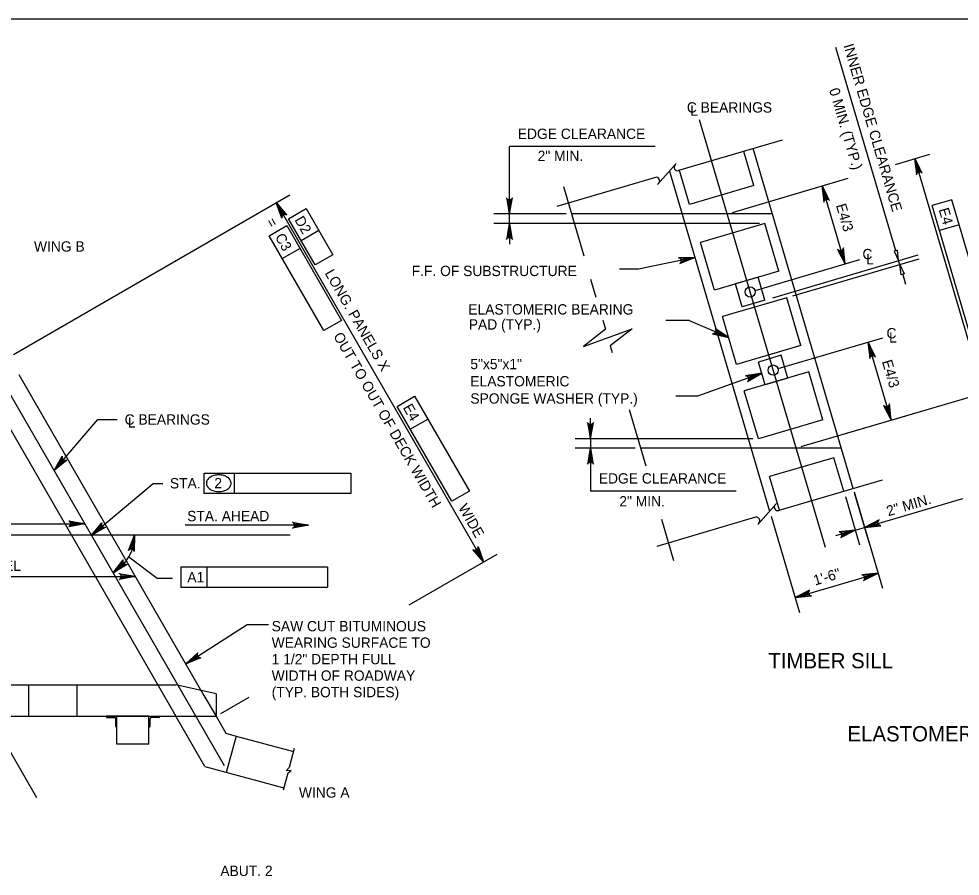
# Model space of a CAD drawing. Extents: x 638268 to 640277, y 295465 to 298435.
# Drawn here: x 639628.9 to 639902.1, y 296983.7 to 297232.5 of the extents above; entities that cross this region are included whole.
import ezdxf

# ---------------------------------------------------------------- set-up
doc = ezdxf.new("R2010")
doc.units = 0
for name, color, linetype in [('2', 7, 'Continuous'), ('3', 7, 'Continuous'), ('4', 7, 'Continuous'), ('7', 7, 'Continuous')]:
    doc.layers.add(name, color=color, linetype=linetype)

msp = doc.modelspace()

# ---------------------------------------------------------------- linework, layer by layer
at = {"layer": '2'}
for p, q in [((639316.46, 297232.46), (640102.46, 297232.46)), ((639614.31, 297134.29), (639674.49, 297030.06)), ((639628.88, 297129.24), (639682.63, 297036.13)), ((639539.28, 297039.18), (639674.46, 297039.18)), ((639631.81, 297030.06), (639631.81, 297039.18)), ((639645.83, 297030.06), (639645.83, 297039.18)), ((639686.14, 297036.58), (639674.46, 297039.18)), ((639686.14, 297036.58), (639686.14, 297030.06)), ((639682.63, 297036.13), (639686.14, 297030.06)), ((639492.13, 297030.06), (639686.14, 297030.06)), ((639492.13, 297030.06), (639686.14, 297030.06)), ((639654.29, 297029.88), (639654.29, 297030.06)), ((639657.38, 297030.06), (639654.29, 297030.06)), ((639654.48, 297029.7), (639656.66, 297029.7)), ((639657.02, 297027.15), (639657.02, 297029.33)), ((639666.62, 297030.06), (639657.38, 297030.06)), ((639657.38, 297026.97), (639657.38, 297030.06)), ((639657.38, 297021.97), (639657.38, 297030.06)), ((639666.62, 297026.97), (639666.62, 297030.06)), ((639666.62, 297030.06), (639669.71, 297030.06)), ((639666.62, 297021.97), (639666.62, 297030.06)), ((639666.98, 297027.15), (639666.98, 297029.33)), ((639669.53, 297029.7), (639667.35, 297029.7)), ((639669.71, 297029.88), (639669.71, 297030.06)), ((639682.91, 297015.46), (639674.49, 297030.06)), ((639686.14, 297030.06), (639688.98, 297025.13)), ((639657.2, 297026.97), (639657.38, 297026.97)), ((639666.8, 297026.97), (639666.62, 297026.97)), ((639688.98, 297025.13), (639691.94, 297024.34)), ((639691.94, 297024.34), (639689.11, 297013.8)), ((639691.94, 297024.34), (639708.62, 297019.87)), ((639666.62, 297021.97), (639657.38, 297021.97)), ((639682.91, 297015.46), (639705.79, 297009.33))]:
    msp.add_line(p, q, dxfattribs=at)
for centre, radius, start, end in [((639654.48, 297029.88), 0.182, 180.0016, 270), ((639656.66, 297029.33), 0.364, 0.0016, 90), ((639667.35, 297029.33), 0.364, 90, 179.9984), ((639669.53, 297029.88), 0.182, 270, 359.9984), ((639657.2, 297027.15), 0.182, 180.0016, 270), ((639666.8, 297027.15), 0.182, 270, 359.9984)]:
    msp.add_arc(centre, radius, start, end, dxfattribs=at)
at = {"layer": '3'}
for p, q in [((639850.43, 297197.27), (639820.41, 297188.43)), ((639871.06, 297096.14), (639842.01, 297194.79)), ((639883.33, 297190.23), (639893.29, 297193.16)), ((639819.72, 297190.5), (639814.31, 297184.36)), ((639908.99, 297123.91), (639888.97, 297191.89)), ((639813.71, 297186.46), (639785.03, 297178.01)), ((639817.76, 297188.28), (639846.82, 297089.63)), ((639786.97, 297183.81), (639792.9, 297163.67)), ((639842.23, 297184.11), (639823.54, 297178.6)), ((639836.01, 297176.29), (639869.64, 297186.19)), ((639847.59, 297175.85), (639789.32, 297175.85)), ((639845.48, 297173.09), (639826.78, 297167.59)), ((639847.72, 297151.52), (639889.91, 297163.95)), ((639853.53, 297152.03), (639890.23, 297162.85)), ((639849.55, 297159.25), (639830.86, 297153.74)), ((639794.88, 297156.95), (639796.43, 297151.7)), ((639843.51, 297157.46), (639836.9, 297155.52)), ((639851.83, 297151.53), (639833.13, 297146.03)), ((639845.46, 297150.86), (639838.85, 297148.91)), ((639798.4, 297145.01), (639799.17, 297142.38)), ((639800.59, 297137.59), (639801.16, 297135.65)), ((639855.9, 297137.69), (639837.21, 297132.18)), ((639850.19, 297134.81), (639843.58, 297132.86)), ((639858.18, 297129.98), (639839.48, 297124.47)), ((639852.13, 297128.2), (639845.53, 297126.25)), ((639856.03, 297108.31), (639913.31, 297125.18)), ((639806.04, 297119.06), (639810.85, 297102.76)), ((639862.25, 297116.13), (639843.56, 297110.62)), ((639867.61, 297107.87), (639809.34, 297107.87)), ((639865.5, 297105.11), (639846.81, 297099.61)), ((639879.48, 297098.62), (639849.47, 297089.78)), ((639848.78, 297091.85), (639843.36, 297085.71)), ((639842.76, 297087.81), (639814.08, 297079.36)), ((639815.4, 297087.29), (639818.93, 297075.3)), ((639708.84, 297020.69), (639707.37, 297015.22)), ((639706.5, 297014.27), (639707.37, 297015.22)), ((639707.96, 297014.36), (639706.5, 297014.27)), ((639706.93, 297013.59), (639707.96, 297014.36)), ((639706.93, 297013.59), (639705.59, 297008.59))]:
    msp.add_line(p, q, dxfattribs=at)
msp.add_lwpolyline([(639890.3, 297189.15), (639889.34, 297188.87), (639888.97, 297191.89)], close=True, dxfattribs=at)
for centre, start, end in [((639820.13, 297189.41), 136.412, 286.412), ((639813.9, 297185.45), 318.5448, 101.0834), ((639849.18, 297090.76), 136.412, 286.412), ((639842.96, 297086.8), 318.5448, 101.0834)]:
    msp.add_arc(centre, 1.02, start, end, dxfattribs=at)
at = {"layer": '4'}
for p, q in [((639883.43, 297165.17), (639866.06, 297224.16)), ((639863.01, 297079.06), (639826.47, 297203.14)), ((639771.31, 297178.85), (639771.31, 297195.39)), ((639813.58, 297195.39), (639771.31, 297195.39)), ((639688.63, 297015.66), (639589.95, 297186.58)), ((639836.01, 297176.29), (639866.38, 297185.23)), ((639868.74, 297161.3), (639862.06, 297183.96)), ((639627.32, 297135.07), (639707.53, 297181.38)), ((639703.63, 297179.13), (639763.8, 297074.9)), ((639899.69, 297179.91), (639894.03, 297178.24)), ((639906.04, 297137.45), (639894.03, 297178.24)), ((639911.7, 297139.12), (639899.69, 297179.91)), ((639707.2, 297174.46), (639712.32, 297177.42)), ((639712.32, 297177.42), (639720.06, 297164)), ((639787.75, 297175.85), (639766.81, 297175.85)), ((639771.31, 297173.09), (639771.31, 297175.85)), ((639714.95, 297161.05), (639707.2, 297174.46)), ((639843.91, 297173.09), (639766.81, 297173.09)), ((639701.52, 297169.49), (639706.64, 297172.44)), ((639706.64, 297172.44), (639722.53, 297144.92)), ((639710.84, 297168.16), (639715.96, 297171.11)), ((639771.31, 297170.09), (639771.31, 297167.09)), ((639901.83, 297172.65), (639896.16, 297170.99)), ((639717.41, 297141.97), (639701.52, 297169.49)), ((639705.35, 297162.87), (639710.46, 297165.82)), ((639720.06, 297164), (639714.95, 297161.05)), ((639842.68, 297153.63), (639873.05, 297162.57)), ((639884.6, 297161.19), (639884.28, 297162.29)), ((639808.76, 297159.78), (639803.23, 297159.78)), ((639885.45, 297158.31), (639886.3, 297155.43)), ((639722.53, 297144.92), (639717.41, 297141.97)), ((639823.57, 297144.87), (639816.72, 297144.87)), ((639849.35, 297130.97), (639879.73, 297139.91)), ((639882.08, 297115.98), (639875.41, 297138.64)), ((639738.67, 297119.98), (639743.78, 297122.93)), ((639743.78, 297122.93), (639759.67, 297095.41)), ((639825.95, 297122.92), (639819.57, 297122.92)), ((639754.56, 297092.46), (639738.67, 297119.98)), ((639639.12, 297101.41), (639651.85, 297116.15)), ((639651.85, 297116.15), (639657.47, 297116.15)), ((639742.49, 297113.35), (639747.61, 297116.31)), ((639794.84, 297113.62), (639794.84, 297116.62)), ((639856.03, 297108.31), (639886.4, 297117.26)), ((639842, 297110.62), (639790.34, 297110.62)), ((639794.84, 297110.62), (639794.84, 297107.87)), ((639807.78, 297107.87), (639790.34, 297107.87)), ((639794.84, 297104.87), (639794.84, 297095.4)), ((639682.7, 297094.75), (639682.7, 297100.65)), ((639682.7, 297100.65), (639725.22, 297100.65)), ((639691.45, 297094.75), (639691.45, 297100.65)), ((639725.22, 297100.65), (639725.22, 297094.75)), ((639649.99, 297082.58), (639667.92, 297097.57)), ((639667.92, 297097.57), (639670.69, 297097.57)), ((639725.22, 297094.75), (639682.7, 297094.75)), ((639759.67, 297095.41), (639754.56, 297092.46)), ((639837.1, 297095.4), (639794.84, 297095.4)), ((639868.82, 297093.85), (639872.96, 297079.78)), ((639871.34, 297095.22), (639879.57, 297067.28)), ((639871.51, 297094.65), (639875.65, 297080.57)), ((639874.38, 297084.88), (639902.9, 297093.29)), ((639847.26, 297088.13), (639855.49, 297060.19)), ((639468.6, 297085.95), (639648.04, 297085.95)), ((639713.02, 297085.52), (639677.21, 297085.52)), ((639871.69, 297084.09), (639865.94, 297082.4)), ((639871.69, 297084.09), (639874.38, 297084.89)), ((639707.69, 297082.58), (639405.47, 297082.58)), ((639742.18, 297062.42), (639767.7, 297077.15)), ((639660.83, 297076.32), (639669.01, 297070.11)), ((639675.94, 297073.48), (639718.45, 297073.48)), ((639675.94, 297073.48), (639675.94, 297067.58)), ((639683.5, 297073.48), (639683.5, 297067.58)), ((639718.45, 297073.48), (639718.45, 297067.58)), ((639471.61, 297070.65), (639662.7, 297070.65)), ((639669.01, 297070.11), (639673.48, 297070.11)), ((639854.22, 297064.5), (639878.3, 297071.6)), ((639598.34, 297068.34), (639634.03, 297006.52)), ((639675.94, 297067.58), (639718.45, 297067.58)), ((639677.37, 297045.24), (639695.2, 297056.69)), ((639695.2, 297056.69), (639701.39, 297056.69)), ((639687.49, 297030.84), (639695.73, 297035.6))]:
    msp.add_line(p, q, dxfattribs=at)
for points in [[(639888.97, 297191.89), (639889.45, 297187.17), (639889.59, 297187.59), (639889.83, 297187.85), (639890.12, 297187.99), (639890.43, 297188.03), (639890.78, 297187.94), (639891.12, 297187.67), (639888.97, 297191.89), (639890.78, 297187.94), (639890.43, 297188.03), (639888.97, 297191.89), (639890.12, 297187.99), (639889.83, 297187.85), (639888.97, 297191.89), (639889.59, 297187.59)], [(639862.06, 297183.96), (639862.54, 297179.25), (639862.68, 297179.66), (639862.92, 297179.92), (639863.21, 297180.06), (639863.52, 297180.1), (639863.88, 297180.01), (639864.21, 297179.74), (639862.06, 297183.96), (639863.88, 297180.01), (639863.52, 297180.1), (639862.06, 297183.96), (639863.21, 297180.06), (639862.92, 297179.92), (639862.06, 297183.96), (639862.68, 297179.66)], [(639703.63, 297179.13), (639706.72, 297175.53), (639706.32, 297175.71), (639705.96, 297175.72), (639705.66, 297175.61), (639705.42, 297175.41), (639705.24, 297175.09), (639705.2, 297174.65), (639703.63, 297179.13), (639705.24, 297175.09), (639705.42, 297175.41), (639703.63, 297179.13), (639705.66, 297175.61), (639705.96, 297175.72), (639703.63, 297179.13), (639706.32, 297175.71)], [(639771.31, 297175.85), (639772.19, 297180.51), (639771.94, 297180.15), (639771.63, 297179.96), (639771.31, 297179.91), (639771, 297179.96), (639770.69, 297180.15), (639770.44, 297180.51), (639771.31, 297175.85), (639770.69, 297180.15), (639771, 297179.96), (639771.31, 297175.85), (639771.31, 297179.91), (639771.63, 297179.96), (639771.31, 297175.85), (639771.94, 297180.15)], [(639771.31, 297173.09), (639770.44, 297168.43), (639770.69, 297168.79), (639771, 297168.97), (639771.31, 297169.03), (639771.63, 297168.97), (639771.94, 297168.79), (639772.19, 297168.43), (639771.31, 297173.09), (639771.94, 297168.79), (639771.63, 297168.97), (639771.31, 297173.09), (639771.31, 297169.03), (639771, 297168.97), (639771.31, 297173.09), (639770.69, 297168.79)], [(639868.74, 297161.3), (639868.26, 297166.02), (639868.12, 297165.61), (639867.87, 297165.34), (639867.59, 297165.2), (639867.27, 297165.16), (639866.92, 297165.25), (639866.58, 297165.53), (639868.74, 297161.3), (639866.92, 297165.25), (639867.27, 297165.16), (639868.74, 297161.3), (639867.59, 297165.2), (639867.87, 297165.34), (639868.74, 297161.3), (639868.12, 297165.61)], [(639825.14, 297163.23), (639808.76, 297159.78)], [(639825.14, 297163.23), (639820.4, 297163.12), (639820.8, 297162.96), (639821.05, 297162.69), (639821.17, 297162.39), (639821.18, 297162.08), (639821.06, 297161.73), (639820.76, 297161.42), (639825.14, 297163.23), (639821.06, 297161.73), (639821.18, 297162.08), (639825.14, 297163.23), (639821.17, 297162.39), (639821.05, 297162.69), (639825.14, 297163.23), (639820.8, 297162.96)], [(639834.91, 297139.97), (639823.41, 297144.94)], [(639799.17, 297142.38), (639792.84, 297137.35), (639806.97, 297142.45), (639800.58, 297137.59)], [(639834.91, 297139.97), (639830.98, 297142.62), (639831.21, 297142.25), (639831.26, 297141.89), (639831.19, 297141.58), (639831.01, 297141.32), (639830.72, 297141.11), (639830.29, 297141.02), (639834.91, 297139.97), (639830.72, 297141.11), (639831.01, 297141.32), (639834.91, 297139.97), (639831.19, 297141.58), (639831.26, 297141.89), (639834.91, 297139.97), (639831.21, 297142.25)], [(639875.41, 297138.64), (639875.89, 297133.93), (639876.03, 297134.34), (639876.27, 297134.61), (639876.56, 297134.75), (639876.87, 297134.78), (639877.22, 297134.69), (639877.56, 297134.42), (639875.41, 297138.64), (639877.22, 297134.69), (639876.87, 297134.78), (639875.41, 297138.64), (639876.56, 297134.75), (639876.27, 297134.61), (639875.41, 297138.64), (639876.03, 297134.34)], [(639844.54, 297129.61), (639825.94, 297122.92)], [(639844.54, 297129.61), (639839.85, 297128.85), (639840.28, 297128.74), (639840.56, 297128.51), (639840.71, 297128.23), (639840.77, 297127.92), (639840.7, 297127.56), (639840.45, 297127.21), (639844.54, 297129.61), (639840.7, 297127.56), (639840.77, 297127.92), (639844.54, 297129.61), (639840.71, 297128.23), (639840.56, 297128.51), (639844.54, 297129.61), (639840.28, 297128.74)], [(639882.08, 297115.98), (639881.6, 297120.7), (639881.47, 297120.29), (639881.22, 297120.02), (639880.94, 297119.88), (639880.62, 297119.85), (639880.27, 297119.93), (639879.93, 297120.21), (639882.08, 297115.98), (639880.27, 297119.93), (639880.62, 297119.85), (639882.08, 297115.98), (639880.94, 297119.88), (639881.22, 297120.02), (639882.08, 297115.98), (639881.47, 297120.29)], [(639794.84, 297110.62), (639795.71, 297115.28), (639795.46, 297114.93), (639795.15, 297114.74), (639794.84, 297114.69), (639794.52, 297114.74), (639794.21, 297114.93), (639793.96, 297115.28), (639794.84, 297110.62), (639794.21, 297114.93), (639794.52, 297114.74), (639794.84, 297110.62), (639794.84, 297114.69), (639795.15, 297114.74), (639794.84, 297110.62), (639795.46, 297114.93)], [(639794.84, 297107.87), (639793.96, 297103.21), (639794.21, 297103.57), (639794.52, 297103.75), (639794.84, 297103.81), (639795.15, 297103.75), (639795.46, 297103.57), (639795.71, 297103.21), (639794.84, 297107.87), (639795.46, 297103.57), (639795.15, 297103.75), (639794.84, 297107.87), (639794.84, 297103.81), (639794.52, 297103.75), (639794.84, 297107.87), (639794.21, 297103.57)], [(639639.12, 297101.41), (639641.5, 297105.51), (639641.46, 297105.07), (639641.57, 297104.73), (639641.77, 297104.48), (639642.05, 297104.32), (639642.4, 297104.26), (639642.83, 297104.36), (639639.12, 297101.41), (639642.4, 297104.26), (639642.05, 297104.32), (639639.12, 297101.41), (639641.77, 297104.48), (639641.57, 297104.73), (639639.12, 297101.41), (639641.46, 297105.07)], [(639648.04, 297085.95), (639643.38, 297085.08), (639643.74, 297085.33), (639643.93, 297085.64), (639643.98, 297085.95), (639643.93, 297086.27), (639643.74, 297086.58), (639643.38, 297086.83), (639648.04, 297085.95), (639643.74, 297086.58), (639643.93, 297086.27), (639648.04, 297085.95), (639643.98, 297085.95), (639643.93, 297085.64), (639648.04, 297085.95), (639643.74, 297085.33)], [(639649.99, 297082.58), (639653, 297086.24), (639652.89, 297085.82), (639652.95, 297085.46), (639653.11, 297085.19), (639653.35, 297084.98), (639653.69, 297084.86), (639654.12, 297084.9), (639649.99, 297082.58), (639653.69, 297084.86), (639653.35, 297084.98), (639649.99, 297082.58), (639653.11, 297085.19), (639652.95, 297085.46), (639649.99, 297082.58), (639652.89, 297085.82)], [(639713.02, 297085.52), (639708.36, 297084.65), (639708.72, 297084.89), (639708.91, 297085.21), (639708.96, 297085.52), (639708.91, 297085.83), (639708.72, 297086.14), (639708.36, 297086.39), (639713.02, 297085.52), (639708.72, 297086.14), (639708.91, 297085.83), (639713.02, 297085.52), (639708.96, 297085.52), (639708.91, 297085.21), (639713.02, 297085.52), (639708.72, 297084.89)], [(639874.38, 297084.88), (639879.1, 297085.36), (639878.68, 297085.5), (639878.42, 297085.75), (639878.28, 297086.03), (639878.24, 297086.35), (639878.33, 297086.7), (639878.6, 297087.04), (639874.38, 297084.88), (639878.33, 297086.7), (639878.24, 297086.35), (639874.38, 297084.88), (639878.28, 297086.03), (639878.42, 297085.75), (639874.38, 297084.88), (639878.68, 297085.5)], [(639871.69, 297084.09), (639866.98, 297083.61), (639867.39, 297083.48), (639867.65, 297083.23), (639867.79, 297082.95), (639867.83, 297082.63), (639867.74, 297082.28), (639867.47, 297081.94), (639871.69, 297084.09), (639867.74, 297082.28), (639867.83, 297082.63), (639871.69, 297084.09), (639867.79, 297082.95), (639867.65, 297083.23), (639871.69, 297084.09), (639867.39, 297083.48)], [(639662.51, 297082.58), (639662.4, 297077.84), (639662.23, 297078.24), (639661.96, 297078.49), (639661.67, 297078.61), (639661.35, 297078.62), (639661.01, 297078.5), (639660.69, 297078.2), (639662.51, 297082.58), (639661.01, 297078.5), (639661.35, 297078.62), (639662.51, 297082.58), (639661.67, 297078.61), (639661.96, 297078.49), (639662.51, 297082.58), (639662.23, 297078.24)], [(639763.8, 297074.9), (639760.72, 297078.5), (639761.11, 297078.31), (639761.48, 297078.31), (639761.77, 297078.42), (639762.02, 297078.62), (639762.2, 297078.94), (639762.23, 297079.37), (639763.8, 297074.9), (639762.2, 297078.94), (639762.02, 297078.62), (639763.8, 297074.9), (639761.77, 297078.42), (639761.48, 297078.31), (639763.8, 297074.9), (639761.11, 297078.31)], [(639656.25, 297071.74), (639659.2, 297075.45), (639659.1, 297075.03), (639659.16, 297074.67), (639659.32, 297074.4), (639659.57, 297074.19), (639659.91, 297074.08), (639660.35, 297074.13), (639656.25, 297071.74), (639659.91, 297074.08), (639659.57, 297074.19), (639656.25, 297071.74), (639659.32, 297074.4), (639659.16, 297074.67), (639656.25, 297071.74), (639659.1, 297075.03)], [(639662.7, 297070.65), (639658.04, 297069.78), (639658.4, 297070.03), (639658.59, 297070.34), (639658.64, 297070.65), (639658.59, 297070.96), (639658.4, 297071.28), (639658.04, 297071.52), (639662.7, 297070.65), (639658.4, 297071.28), (639658.59, 297070.96), (639662.7, 297070.65), (639658.64, 297070.65), (639658.59, 297070.34), (639662.7, 297070.65), (639658.4, 297070.03)], [(639878.3, 297071.6), (639873.58, 297071.12), (639873.99, 297070.98), (639874.26, 297070.73), (639874.4, 297070.45), (639874.44, 297070.13), (639874.35, 297069.78), (639874.07, 297069.44), (639878.3, 297071.6), (639874.35, 297069.78), (639874.44, 297070.13), (639878.3, 297071.6), (639874.4, 297070.45), (639874.26, 297070.73), (639878.3, 297071.6), (639873.99, 297070.98)], [(639854.22, 297064.5), (639858.94, 297064.98), (639858.52, 297065.12), (639858.26, 297065.37), (639858.12, 297065.65), (639858.08, 297065.97), (639858.17, 297066.32), (639858.44, 297066.66), (639854.22, 297064.5), (639858.17, 297066.32), (639858.08, 297065.97), (639854.22, 297064.5), (639858.12, 297065.65), (639858.26, 297065.37), (639854.22, 297064.5), (639858.52, 297065.12)], [(639677.37, 297045.24), (639680.82, 297048.49), (639680.66, 297048.09), (639680.67, 297047.73), (639680.79, 297047.43), (639681.01, 297047.2), (639681.33, 297047.04), (639681.77, 297047.02), (639677.37, 297045.24), (639681.33, 297047.04), (639681.01, 297047.2), (639677.37, 297045.24), (639680.79, 297047.43), (639680.67, 297047.73), (639677.37, 297045.24), (639680.66, 297048.09)]]:
    msp.add_lwpolyline(points, dxfattribs=at)
for points in [[(639863.39, 297181.23), (639862.43, 297180.94), (639862.06, 297183.96)], [(639705.56, 297176.78), (639704.7, 297176.28), (639703.63, 297179.13)], [(639771.81, 297178.85), (639770.81, 297178.85), (639771.31, 297175.85)], [(639771.81, 297170.09), (639770.81, 297170.09), (639771.31, 297173.09)], [(639883.91, 297165.31), (639882.95, 297165.03), (639884.28, 297162.29)], [(639825.14, 297163.23), (639822.26, 297162.37), (639822.15, 297162.86)], [(639868.37, 297164.32), (639867.41, 297164.04), (639868.74, 297161.3)], [(639885.93, 297158.45), (639884.97, 297158.17), (639884.6, 297161.19)], [(639834.91, 297139.97), (639832.06, 297140.93), (639832.26, 297141.39)], [(639876.74, 297135.91), (639875.78, 297135.62), (639875.41, 297138.64)], [(639844.54, 297129.61), (639841.8, 297128.36), (639841.63, 297128.83)], [(639881.71, 297119), (639880.76, 297118.72), (639882.08, 297115.98)], [(639795.34, 297113.62), (639794.34, 297113.62), (639794.84, 297110.62)], [(639795.34, 297104.87), (639794.34, 297104.87), (639794.84, 297107.87)], [(639877.12, 297086.21), (639877.4, 297085.25), (639874.38, 297084.89)], [(639651.82, 297084.71), (639652.41, 297084), (639649.99, 297082.58)], [(639868.67, 297083.73), (639868.95, 297082.77), (639871.69, 297084.09)], [(639762.74, 297077.75), (639761.87, 297077.25), (639763.8, 297074.9)], [(639875.28, 297071.23), (639875.56, 297070.27), (639878.3, 297071.6)], [(639856.96, 297065.83), (639857.24, 297064.87), (639854.22, 297064.5)], [(639680.32, 297046.58), (639679.82, 297047.36), (639677.74, 297045.47)]]:
    msp.add_lwpolyline(points, close=True, dxfattribs=at)
for centre, radius, start, end in [((639685.95, 297097.13), 2.75, 124.109, 148.5507), ((639686.55, 297096.24), 3.82, 105.6708, 124.109), ((639686.94, 297094.84), 5.27, 90, 105.6708), ((639686.94, 297094.84), 5.27, 74.3292, 90), ((639687.33, 297096.24), 3.82, 55.891, 74.3292), ((639687.93, 297097.13), 2.75, 31.4493, 55.891), ((639685.03, 297097.69), 1.68, 148.5507, 180), ((639685.03, 297097.69), 1.68, 180, 211.4493), ((639685.95, 297098.25), 2.75, 211.4493, 235.891), ((639687.93, 297098.25), 2.75, 304.109, 328.5507), ((639688.84, 297097.69), 1.68, 0, 31.4493), ((639688.84, 297097.69), 1.68, 328.5507, 0), ((639686.55, 297099.13), 3.82, 235.891, 254.3292), ((639686.94, 297100.53), 5.27, 254.3292, 270), ((639686.94, 297100.53), 5.27, 270, 285.6708), ((639687.33, 297099.13), 3.82, 285.6708, 304.109), ((639649.99, 297082.58), 12.52, 299.9992, 0.0004)]:
    msp.add_arc(centre, radius, start, end, dxfattribs=at)
at = {"layer": '7'}
for p, q in [((639842.23, 297184.11), (639839.32, 297194)), ((639823.54, 297178.6), (639820.63, 297188.49)), ((639849.55, 297159.25), (639845.48, 297173.09)), ((639830.86, 297153.74), (639826.78, 297167.59)), ((639845.46, 297150.86), (639843.51, 297157.46)), ((639838.85, 297148.91), (639836.9, 297155.52)), ((639855.9, 297137.69), (639851.83, 297151.53)), ((639837.21, 297132.18), (639833.13, 297146.03)), ((639852.13, 297128.2), (639850.19, 297134.81)), ((639845.53, 297126.25), (639843.58, 297132.86)), ((639862.25, 297116.13), (639858.18, 297129.98)), ((639843.56, 297110.62), (639839.48, 297124.47)), ((639868.38, 297095.35), (639865.5, 297105.11)), ((639849.68, 297089.85), (639846.81, 297099.61))]:
    msp.add_line(p, q, dxfattribs=at)
for centre in [(639841.18, 297153.19), (639847.86, 297130.53)]:
    msp.add_circle(centre, 1.48, dxfattribs=at)

# ---------------------------------------------------------------- texts
at = {"layer": '3'}
for s, p in [('TIMBER SILL', (639846.46, 297043.99)), ('ELASTOMERIC BEARING PAD ARRANGEMENTS', (639869.42, 297022.77))]:
    msp.add_text(s, height=4.4292, dxfattribs=at).set_placement(p)
at = {"layer": '4'}
for s, rotation, p in [('INNER EDGE CLEARANCE', 286.412, (639868.21, 297224.73)), ('0 MIN. (TYP.)', 286.412, (639864.06, 297211.89)), ('E4/3', 286.412, (639866.04, 297178.35)), ('E4', 286.4738, (639895.87, 297177.12)), ('=', 300, (639700.55, 297173.65)), ('D2', 300, (639708.82, 297174.14)), ('C3', 300, (639703.14, 297169.17)), ('LONG. PANELS X', 300, (639717.58, 297158.67)), ('OUT TO OUT OF DECK WIDTH', 300, (639720.08, 297140.43)), ('E4/3', 286.412, (639879.39, 297133.03)), ('E4', 300, (639740.29, 297119.65)), ('2" MIN.', 16.4163, (639881.27, 297088.08)), ('WIDE', 300, (639756.32, 297090.62)), ('A1', 359.9382, (639677.8, 297068.93)), ('1\'-6"', 16.4163, (639860.03, 297067.99))]:
    msp.add_text(s, height=3, rotation=rotation, dxfattribs=at).set_placement(p)
for s, p in [('C BEARINGS', (639822.8, 297205.25)), ('L', (639823.82, 297204.34)), ('EDGE CLEARANCE', (639773.73, 297197.59)), ('2" MIN.', (639779.49, 297191.18)), ('WING B', (639633.29, 297164.9)), ('C', (639873.77, 297162.69)), ('L', (639874.83, 297161.17)), ('F.F. OF SUBSTRUCTURE', (639742.94, 297157.81)), ('ELASTOMERIC BEARING', (639759.36, 297146.65)), ('PAD (TYP.)', (639759.51, 297142.27)), ('C', (639880.75, 297139.73)), ('L', (639881.5, 297138.51)), ('5"x5"x1"', (639759.96, 297130.79)), ('ELASTOMERIC', (639759.96, 297125.79)), ('SPONGE WASHER (TYP.)', (639759.96, 297120.79)), ('C BEARINGS', (639659.6, 297114.69)), ('L', (639660.55, 297113.83)), ('STA.', (639672.74, 297096.18)), ('2', (639685.64, 297096.23)), ('EDGE CLEARANCE', (639797.25, 297097.6)), ('2" MIN.', (639803.2, 297090.95)), ('STA. AHEAD', (639677.75, 297086.67)), ('OUT TO OUT LONGITUDINAL PANEL', (639559.76, 297072.27)), ('SAW CUT BITUMINOUS', (639702.29, 297054.71)), ('WEARING SURFACE TO', (639702.29, 297049.93)), ('1 1/2" DEPTH FULL', (639702.29, 297045.15)), ('WIDTH OF ROADWAY', (639702.29, 297040.37)), ('(TYP. BOTH SIDES)', (639702.29, 297035.59)), ('WING A', (639710.19, 297006.45)), ('ABUT. 2', (639687.39, 296983.71))]:
    msp.add_text(s, height=3, dxfattribs=at).set_placement(p)

doc.saveas('drawing.dxf')
